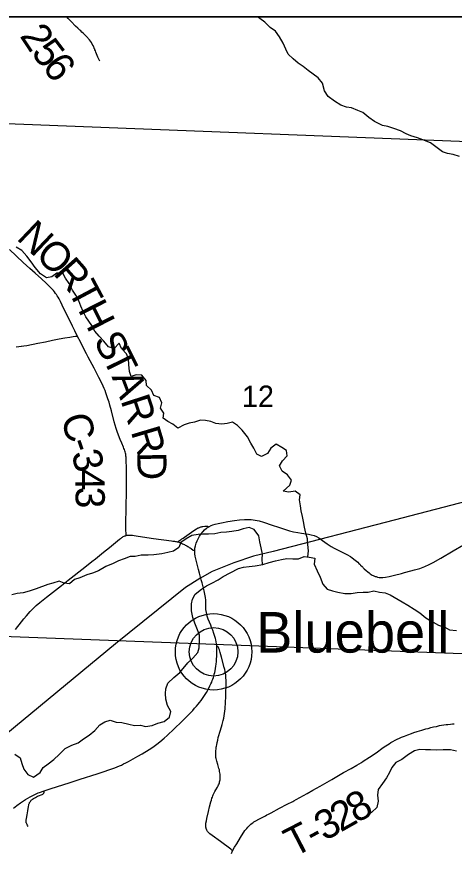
# Model space of a CAD drawing. Extents: x 0 to 34, y 0 to 22.
# Drawn here: x 4.44 to 5.291, y 19.271 to 20.9 of the extents above; entities that cross this region are included whole.
import ezdxf

# ---------------------------------------------------------------- set-up
doc = ezdxf.new("R2010")
doc.units = 0
for name, color, linetype in [('GM_X_Corporation', 7, 'Continuous'), ('GM_X_County_Road', 7, 'Continuous'), ('GM_X_County_Road_Text', 7, 'Continuous'), ('GM_X_Minor_River', 7, 'Continuous'), ('GM_X_Rail_Line', 7, 'Continuous'), ('GM_X_Section_Text', 7, 'Continuous'), ('GM_X_State_Route', 7, 'Continuous'), ('GM_X_Township_Road', 7, 'Continuous'), ('GM_X_Township_Road_Text', 7, 'Continuous'), ('GM_X_Unincorporated', 7, 'Continuous'), ('GM_X_Unincorporated_Location', 7, 'Continuous'), ('GM_X_Unincorporated_Text', 7, 'Continuous'), ('SH_Data', 7, 'Continuous')]:
    doc.layers.add(name, color=color, linetype=linetype)

msp = doc.modelspace()

# ---------------------------------------------------------------- linework, layer by layer
at = {"layer": 'GM_X_Corporation'}
for points in [[(8.9, 20.9), (2.1, 20.9), (2.1, 15.6606)], [(8.9, 20.9), (3.3886, 20.9), (3.3869, 20.7918), (3.3724, 19.7263), (3.3691, 19.5041), (3.3642, 18.7005)]]:
    msp.add_lwpolyline(points, dxfattribs=at)
for points in [[(5.4364, 20.9), (4.4076, 20.9), (4.4032, 20.6929), (5.4344, 20.6525)], [(5.4344, 20.6525), (5.4328, 20.6183), (5.4095, 19.6556), (4.3939, 19.6935), (4.4032, 20.6929)]]:
    msp.add_lwpolyline(points, close=True, dxfattribs=at)
at = {"layer": 'GM_X_County_Road'}
for points in [[(4.5583, 20.2776), (4.553, 20.2883), (4.5487, 20.2972), (4.5286, 20.3386), (4.5249, 20.3457), (4.5222, 20.3507), (4.5204, 20.3537), (4.5187, 20.3566), (4.5172, 20.359), (4.5155, 20.3613), (4.5135, 20.364), (4.5112, 20.3666), (4.5084, 20.3698), (4.5053, 20.3731), (4.4974, 20.3811), (4.4883, 20.3896), (4.4756, 20.4007), (4.4653, 20.4095), (4.4522, 20.4211), (4.4256, 20.4464)], [(4.5583, 20.2776), (4.5541, 20.277), (4.55, 20.2765), (4.5433, 20.2755), (4.5334, 20.2739), (4.5224, 20.2718), (4.5097, 20.2692), (4.4958, 20.2664), (4.4812, 20.2634), (4.4599, 20.2592), (4.4538, 20.2583), (4.4495, 20.2577), (4.4483, 20.2576), (4.444, 20.257), (4.4387, 20.2566)], [(4.6531, 19.8898), (4.6528, 19.8926), (4.6526, 19.8954), (4.6524, 19.898), (4.6522, 19.9016), (4.6521, 19.9071), (4.6521, 19.9114), (4.6521, 19.9195), (4.6527, 19.9362), (4.6531, 19.9467), (4.6535, 19.9743), (4.6536, 19.9923), (4.6537, 20.0096), (4.6536, 20.019), (4.6534, 20.0258), (4.6531, 20.0314), (4.6528, 20.037), (4.6526, 20.0424), (4.6524, 20.0443), (4.6522, 20.0462), (4.6519, 20.0481), (4.6515, 20.05), (4.6508, 20.0525), (4.6501, 20.0549), (4.6493, 20.057), (4.6484, 20.0594), (4.6475, 20.0619), (4.6444, 20.0693), (4.6412, 20.0768), (4.6361, 20.0901), (4.6333, 20.0983), (4.6295, 20.1114), (4.6242, 20.1325), (4.6213, 20.1433), (4.6195, 20.1494), (4.6174, 20.1558), (4.6154, 20.1617), (4.6134, 20.1676), (4.6117, 20.172), (4.61, 20.1763), (4.6059, 20.1854), (4.5999, 20.1977), (4.5903, 20.2159), (4.5789, 20.2372), (4.5755, 20.2438), (4.5682, 20.2582), (4.5637, 20.2669), (4.5583, 20.2776)], [(4.7534, 19.8773), (4.7549, 19.8786), (4.7567, 19.88), (4.7585, 19.8814), (4.7597, 19.8822), (4.7609, 19.8831), (4.7635, 19.8847), (4.7661, 19.8864), (4.7709, 19.8897), (4.7757, 19.8933), (4.7843, 19.8993), (4.7895, 19.9026), (4.7917, 19.9038), (4.7929, 19.9044), (4.794, 19.905), (4.7953, 19.9056), (4.7966, 19.906), (4.7979, 19.9065), (4.7992, 19.9069), (4.8006, 19.9072), (4.802, 19.9075), (4.8057, 19.908), (4.8087, 19.9081), (4.8099, 19.908), (4.8111, 19.9078), (4.8126, 19.9073), (4.8138, 19.9069)], [(4.4377, 19.7069), (4.4493, 19.7218), (4.4539, 19.7277), (4.4587, 19.7334), (4.466, 19.7417), (4.4721, 19.7479), (4.4748, 19.7505), (4.478, 19.7534), (4.4846, 19.759), (4.4977, 19.7695), (4.527, 19.7925), (4.5402, 19.8028), (4.5725, 19.828), (4.5861, 19.8388), (4.5929, 19.8442), (4.6089, 19.8571), (4.6204, 19.8666), (4.6281, 19.8729), (4.6401, 19.8827), (4.6415, 19.8838), (4.6429, 19.8848), (4.6443, 19.8858), (4.6458, 19.8868), (4.6472, 19.8875), (4.6488, 19.8883), (4.6501, 19.8889), (4.6514, 19.8894), (4.6531, 19.8898)], [(4.6531, 19.8898), (4.6546, 19.8902), (4.6562, 19.8905), (4.6575, 19.8906), (4.659, 19.8907), (4.6605, 19.8907), (4.6621, 19.8906), (4.6636, 19.8905), (4.665, 19.8903), (4.6683, 19.8898), (4.6763, 19.8886), (4.7057, 19.884), (4.7411, 19.8792), (4.7439, 19.8788), (4.7468, 19.8784), (4.7485, 19.8782), (4.7501, 19.878), (4.7518, 19.8777), (4.7534, 19.8773)], [(4.7534, 19.8773), (4.7552, 19.8767), (4.757, 19.876), (4.7589, 19.8753), (4.7607, 19.8745), (4.7625, 19.8737), (4.7644, 19.8728), (4.766, 19.8721), (4.7677, 19.8712), (4.7694, 19.8703), (4.771, 19.8694), (4.7725, 19.8686), (4.7741, 19.8676), (4.7757, 19.8667), (4.7775, 19.8655), (4.779, 19.8645), (4.7834, 19.8615), (4.7864, 19.8596)]]:
    msp.add_lwpolyline(points, dxfattribs=at)
at = {"layer": 'GM_X_Minor_River'}
for points in [[(5.0071, 20.7954), (4.9972, 20.8029), (4.9877, 20.8096), (4.9774, 20.8178), (4.9679, 20.8268), (4.9636, 20.8366), (4.9583, 20.8487), (4.9513, 20.8611), (4.9433, 20.8717), (4.933, 20.8791), (4.9227, 20.8896), (4.9128, 20.8963), (4.9084, 20.9)], [(5.3011, 20.628), (5.289, 20.6317), (5.278, 20.6334), (5.2682, 20.6371), (5.2446, 20.6543), (5.2302, 20.6602), (5.2196, 20.6643), (5.2067, 20.6679), (5.1972, 20.672), (5.1862, 20.6776), (5.1737, 20.6824), (5.1619, 20.686), (5.1517, 20.6882), (5.1357, 20.696), (5.1247, 20.7038), (5.1129, 20.7132), (5.1034, 20.7172), (5.0909, 20.7228), (5.0811, 20.7242), (5.0701, 20.7279), (5.0579, 20.7353), (5.0457, 20.7447), (5.0384, 20.756), (5.0345, 20.7703), (5.0261, 20.7812), (5.0071, 20.7954)], [(5.0062, 19.8481), (5.0077, 19.8599), (5.0065, 19.872), (5.0053, 19.883), (5.0025, 19.894), (4.9994, 19.9057), (4.9978, 19.917), (4.9958, 19.9269), (4.9934, 19.9378), (4.9918, 19.9477), (4.9898, 19.959), (4.9916, 19.9689), (4.9814, 19.976), (4.9693, 19.9739), (4.9579, 19.9761), (4.9711, 19.988), (4.9744, 19.9975), (4.9667, 20.008), (4.9561, 20.0151), (4.9511, 20.0257), (4.9571, 20.0352), (4.966, 20.0451), (4.9648, 20.055), (4.9553, 20.0609), (4.9443, 20.0673), (4.9345, 20.0596), (4.9278, 20.0497), (4.9161, 20.0439), (4.9067, 20.0483), (4.9013, 20.0596), (4.8951, 20.0694), (4.889, 20.0822), (4.8787, 20.0946), (4.8691, 20.104), (4.8596, 20.1103), (4.8494, 20.1079), (4.8389, 20.1063), (4.8275, 20.1077), (4.8177, 20.1118), (4.807, 20.1139), (4.7972, 20.1142), (4.7855, 20.1103), (4.7757, 20.1083), (4.7655, 20.1055), (4.7535, 20.0986), (4.7436, 20.1068), (4.7341, 20.112), (4.7246, 20.118), (4.7264, 20.1279), (4.7199, 20.1377), (4.7221, 20.1483), (4.7178, 20.1588), (4.7068, 20.1625), (4.7022, 20.1727), (4.6927, 20.1817), (4.6918, 20.1919), (4.683, 20.2021), (4.6721, 20.2027), (4.6623, 20.1992), (4.6592, 20.2094), (4.6583, 20.223), (4.6571, 20.234), (4.6532, 20.2438), (4.644, 20.2539), (4.639, 20.2641), (4.6293, 20.2541), (4.6187, 20.2574), (4.6091, 20.2683), (4.6, 20.2781), (4.592, 20.2879), (4.5858, 20.2984), (4.5743, 20.3157), (4.5689, 20.3259), (4.5647, 20.3361), (4.5608, 20.3466), (4.5551, 20.3579), (4.5482, 20.3677), (4.542, 20.3802), (4.5347, 20.3907), (4.529, 20.4016), (4.518, 20.4007), (4.5082, 20.3938), (4.4981, 20.3914), (4.4859, 20.3996), (4.4756, 20.4117), (4.4683, 20.423), (4.4599, 20.4339), (4.45, 20.4447), (4.4386, 20.4511)], [(4.918, 19.8332), (4.9171, 19.8434), (4.9182, 19.8533), (4.9154, 19.8658), (4.9127, 19.8771), (4.9111, 19.8892), (4.9019, 19.9013), (4.892, 19.9053), (4.8807, 19.9029), (4.8709, 19.8998), (4.8581, 19.8978), (4.8483, 19.8965), (4.8369, 19.8953), (4.8252, 19.8932), (4.8128, 19.8924), (4.8029, 19.8923), (4.7931, 19.8914), (4.7803, 19.8897), (4.7694, 19.8832), (4.7592, 19.8763), (4.7555, 19.8664), (4.745, 19.8591), (4.7341, 19.8567), (4.7224, 19.8543), (4.7065, 19.8518), (4.6959, 19.8514), (4.6819, 19.8512), (4.6706, 19.8488), (4.6604, 19.8491), (4.6487, 19.8444), (4.6378, 19.8401), (4.6273, 19.8351), (4.6133, 19.8293), (4.5987, 19.8212), (4.5874, 19.8165), (4.5761, 19.813), (4.5629, 19.8075), (4.5523, 19.804), (4.5426, 19.7959), (4.532, 19.7966), (4.5225, 19.8007), (4.5104, 19.7971), (4.5002, 19.794), (4.4776, 19.7862), (4.4644, 19.7815), (4.4524, 19.7783), (4.441, 19.7767), (4.4305, 19.7743)], [(4.4729, 19.419), (4.4853, 19.4282), (4.4912, 19.4378), (4.501, 19.4454), (4.5119, 19.4535), (4.5224, 19.4631), (4.5344, 19.475), (4.5472, 19.4815), (4.5592, 19.4862), (4.5698, 19.4935), (4.5807, 19.5012), (4.5919, 19.51), (4.6017, 19.5208), (4.6114, 19.5269), (4.6216, 19.5304), (4.6334, 19.5264), (4.6447, 19.5254), (4.6583, 19.5225), (4.6693, 19.5199), (4.6807, 19.5204), (4.6905, 19.5179), (4.7037, 19.5195), (4.7147, 19.5242), (4.7267, 19.5274), (4.7369, 19.5358), (4.7398, 19.5468), (4.7333, 19.5585), (4.7297, 19.5713), (4.7293, 19.5819), (4.7303, 19.5914), (4.734, 19.6021), (4.7456, 19.6132), (4.7569, 19.6228), (4.7726, 19.6419), (4.7824, 19.6511), (4.7925, 19.6618), (4.7947, 19.6713), (4.7953, 19.6838), (4.7956, 19.6955), (4.7917, 19.7061), (4.7863, 19.7193), (4.7824, 19.7303), (4.78, 19.7431), (4.7799, 19.7564), (4.7821, 19.7659), (4.7869, 19.7758), (4.7993, 19.785), (4.8091, 19.7919), (4.8193, 19.797), (4.8321, 19.8035), (4.8418, 19.8101), (4.855, 19.817), (4.8712, 19.8252), (4.881, 19.8279), (4.8923, 19.8295), (4.904, 19.8304), (4.9184, 19.8332), (4.9312, 19.8372), (4.9433, 19.8403), (4.9549, 19.8431), (4.9655, 19.8447), (4.9769, 19.8445), (4.9882, 19.8446), (4.9991, 19.8489), (5.009, 19.8478), (5.0196, 19.8453), (5.0182, 19.8339), (5.0243, 19.8207), (5.0305, 19.8086), (5.0355, 19.7951), (5.0439, 19.7853), (5.0541, 19.782), (5.0647, 19.7795), (5.0784, 19.7769), (5.0905, 19.7771), (5.1022, 19.7787), (5.1139, 19.7792), (5.1237, 19.7797), (5.1347, 19.7817), (5.1456, 19.7795), (5.1566, 19.7781), (5.1661, 19.7741), (5.1897, 19.7607), (5.2007, 19.7544), (5.2132, 19.7462), (5.2242, 19.7391), (5.236, 19.7294), (5.2497, 19.7208), (5.2604, 19.7152), (5.2725, 19.7112), (5.282, 19.7063), (5.2952, 19.7046)], [(5.2954, 19.4697), (5.2836, 19.4726), (5.2697, 19.4725), (5.2564, 19.4716), (5.2451, 19.4726), (5.2349, 19.4721), (5.2239, 19.4731), (5.2134, 19.4703), (5.2021, 19.4634), (5.1893, 19.4538), (5.1773, 19.4476), (5.1698, 19.4381), (5.165, 19.4285), (5.159, 19.4179), (5.1512, 19.4068), (5.1433, 19.3954), (5.1419, 19.384), (5.1428, 19.3722), (5.1406, 19.3601), (5.1305, 19.3509), (5.1207, 19.344), (5.1222, 19.3428)], [(4.4362, 19.4641), (4.4465, 19.457), (4.45, 19.446), (4.4538, 19.4347), (4.4615, 19.4242), (4.4729, 19.419)]]:
    msp.add_lwpolyline(points, dxfattribs=at)
at = {"layer": 'GM_X_Rail_Line'}
msp.add_lwpolyline([(7.1041, 20.4576), (6.548, 20.2811), (6.4552, 20.2522), (5.6204, 20.0355), (5.1742, 19.9198), (4.9387, 19.8589), (4.9007, 19.8493), (4.8622, 19.8368), (4.8204, 19.8197), (4.7961, 19.8057), (4.7682, 19.7883), (4.6322, 19.6788), (3.9277, 19.0962), (3.874, 19.0476), (3.8339, 19.0097), (3.7908, 18.9611), (3.75, 18.9158), (3.7169, 18.8748), (3.6829, 18.8279), (3.1625, 18.0833)], dxfattribs=at)
at = {"layer": 'GM_X_State_Route'}
msp.add_lwpolyline([(4.4337, 19.359), (4.4402, 19.3639), (4.4475, 19.369), (4.4573, 19.3754), (4.4664, 19.3807), (4.4703, 19.383), (4.4739, 19.3849), (4.4763, 19.3861), (4.4788, 19.3872), (4.4815, 19.3884), (4.4843, 19.3894), (4.4935, 19.3927), (4.5047, 19.3962), (4.5439, 19.4088), (4.5635, 19.4151), (4.5966, 19.4259), (4.6099, 19.4303), (4.6193, 19.4335), (4.6248, 19.4354), (4.6307, 19.4376), (4.6355, 19.4394), (4.6399, 19.4412), (4.6435, 19.4428), (4.6478, 19.4448), (4.6525, 19.4471), (4.6576, 19.4498), (4.6618, 19.452), (4.6663, 19.4546), (4.6754, 19.4598), (4.6838, 19.4647), (4.6973, 19.4731), (4.7026, 19.4765), (4.7072, 19.4796), (4.7123, 19.4833), (4.7182, 19.4878), (4.7268, 19.495), (4.7324, 19.5), (4.7464, 19.5132), (4.761, 19.5275), (4.7758, 19.5426), (4.7823, 19.5492), (4.786, 19.5532), (4.7898, 19.5575), (4.7928, 19.5611), (4.7957, 19.5647), (4.7985, 19.5683), (4.8013, 19.5723), (4.8038, 19.5759), (4.8064, 19.58), (4.8088, 19.584), (4.8115, 19.5886), (4.8136, 19.5926), (4.8158, 19.5969), (4.8175, 19.6006), (4.8192, 19.6043), (4.8204, 19.6073), (4.8214, 19.6101), (4.8224, 19.6133), (4.8233, 19.6161), (4.8242, 19.6194), (4.825, 19.6227), (4.8258, 19.6264), (4.8266, 19.6307), (4.8272, 19.6352), (4.8278, 19.6393), (4.8283, 19.6444), (4.8287, 19.6493), (4.829, 19.6542), (4.8292, 19.6593), (4.8293, 19.6636), (4.8292, 19.668), (4.8289, 19.6746), (4.8287, 19.6791), (4.8281, 19.6829), (4.8272, 19.6865), (4.8265, 19.6894), (4.8249, 19.6947), (4.8235, 19.6988), (4.8212, 19.7052), (4.8189, 19.7109), (4.8173, 19.7149), (4.8125, 19.727), (4.8105, 19.7329), (4.809, 19.7396), (4.8081, 19.7458), (4.8078, 19.7533), (4.8076, 19.7637), (4.8071, 19.7692), (4.8061, 19.7753), (4.8047, 19.7819), (4.802, 19.7927), (4.8007, 19.7974), (4.8, 19.7998), (4.799, 19.8034), (4.7976, 19.8088), (4.7955, 19.8166), (4.7935, 19.8238), (4.7908, 19.834), (4.7882, 19.8443), (4.7872, 19.8498), (4.7866, 19.8542), (4.7864, 19.8596), (4.7867, 19.8649), (4.7876, 19.8699), (4.7889, 19.8748), (4.7907, 19.8795), (4.7926, 19.8835), (4.7954, 19.8884), (4.7987, 19.893), (4.8023, 19.8974), (4.8055, 19.9005), (4.8093, 19.9038), (4.8138, 19.9069), (4.818, 19.9091), (4.8215, 19.9105), (4.8257, 19.9119), (4.8318, 19.9133), (4.8385, 19.9145), (4.8508, 19.9167), (4.8637, 19.9188), (4.8736, 19.92), (4.8829, 19.9208), (4.8892, 19.9209), (4.8961, 19.9208), (4.9036, 19.9198), (4.9115, 19.918), (4.9199, 19.9156), (4.9371, 19.91), (4.9494, 19.9058), (4.9606, 19.9021), (4.9707, 19.899), (4.9784, 19.897), (4.9869, 19.8954), (4.9937, 19.8943), (5.0072, 19.8921), (5.0127, 19.8911), (5.0182, 19.8897), (5.0229, 19.8878), (5.0273, 19.8853), (5.0345, 19.8803), (5.0441, 19.8734), (5.0513, 19.8686), (5.0577, 19.8649), (5.0637, 19.8618), (5.0704, 19.8586), (5.0743, 19.8567), (5.0766, 19.8556), (5.0821, 19.8527), (5.0891, 19.8486), (5.0927, 19.8461), (5.0982, 19.8419), (5.1034, 19.8375), (5.1056, 19.8354), (5.1073, 19.8337), (5.1079, 19.833), (5.1088, 19.832), (5.1117, 19.8291), (5.113, 19.8279), (5.1138, 19.8271), (5.1159, 19.825), (5.1194, 19.8219), (5.1203, 19.8211), (5.1221, 19.8195), (5.123, 19.8187), (5.1253, 19.8169), (5.1272, 19.8154), (5.1296, 19.8137), (5.1312, 19.8128), (5.1332, 19.8118), (5.1371, 19.8102), (5.1388, 19.8097), (5.1416, 19.8088), (5.1451, 19.8082), (5.1487, 19.808), (5.1523, 19.8081), (5.1571, 19.8087), (5.1644, 19.8102), (5.1747, 19.8126), (5.1885, 19.816), (5.1945, 19.8175), (5.1969, 19.8182), (5.2137, 19.8227), (5.2238, 19.8258), (5.2336, 19.8294), (5.2421, 19.8331), (5.2503, 19.8374), (5.2649, 19.8457), (5.2889, 19.8599), (5.3087, 19.8717)], dxfattribs=at)
at = {"layer": 'GM_X_Township_Road'}
msp.add_line((4.8576, 19.2704), (4.8599, 19.2758), dxfattribs=at)
for points in [[(4.6017, 20.8135), (4.598, 20.8214), (4.5953, 20.8277), (4.5939, 20.8311), (4.593, 20.8333), (4.5921, 20.8355), (4.5916, 20.8366), (4.5909, 20.8383), (4.5904, 20.8394), (4.59, 20.8405), (4.5885, 20.8438), (4.587, 20.8468), (4.5851, 20.8497), (4.5834, 20.8523), (4.5813, 20.8553), (4.5792, 20.8576), (4.5781, 20.859), (4.5764, 20.8609), (4.5739, 20.8635), (4.5716, 20.8656), (4.5694, 20.8678), (4.5667, 20.8702), (4.5645, 20.8724), (4.5627, 20.8741), (4.5591, 20.8775), (4.5546, 20.8818), (4.5458, 20.8905), (4.5403, 20.8965), (4.5376, 20.8999), (4.5376, 20.9)], [(4.8599, 19.2758), (4.8561, 19.2789), (4.8364, 19.2939), (4.82, 19.3057), (4.8156, 19.3088), (4.8145, 19.3098), (4.8134, 19.3109), (4.8123, 19.3121), (4.8113, 19.3134), (4.8104, 19.3147), (4.8097, 19.3161), (4.809, 19.3176), (4.8085, 19.3188), (4.8082, 19.3201), (4.8078, 19.3217), (4.8077, 19.3233), (4.8076, 19.3246), (4.8077, 19.3259), (4.8078, 19.3277), (4.8081, 19.3297), (4.809, 19.3342), (4.81, 19.3389), (4.8131, 19.3522), (4.815, 19.3613), (4.8174, 19.371), (4.8185, 19.3746), (4.8196, 19.3782), (4.8205, 19.3805), (4.8212, 19.3826), (4.822, 19.3844), (4.8227, 19.3859), (4.8233, 19.3872), (4.8241, 19.3885), (4.8256, 19.3914), (4.8275, 19.3945), (4.8306, 19.3998), (4.8318, 19.4021), (4.8327, 19.4042), (4.8335, 19.4061), (4.8342, 19.4082), (4.8346, 19.4098), (4.835, 19.4117), (4.8354, 19.4139), (4.8356, 19.4159), (4.8358, 19.418), (4.8358, 19.4201), (4.8357, 19.4226), (4.8355, 19.4249), (4.8352, 19.4276), (4.8347, 19.4303), (4.8341, 19.4332), (4.8333, 19.4362), (4.831, 19.4438), (4.8292, 19.45), (4.828, 19.4552), (4.8275, 19.4577), (4.8272, 19.4601), (4.8271, 19.4627), (4.8271, 19.4651), (4.8271, 19.4678), (4.8273, 19.4707), (4.8276, 19.4741), (4.8281, 19.4775), (4.8285, 19.4798), (4.8289, 19.4823), (4.8298, 19.4866), (4.8309, 19.4914), (4.8321, 19.4962), (4.8362, 19.5104), (4.8396, 19.5215), (4.8416, 19.5292), (4.8426, 19.534), (4.8435, 19.5388), (4.8442, 19.5432), (4.8449, 19.5479), (4.8454, 19.5521), (4.8457, 19.5564), (4.846, 19.5616), (4.8462, 19.5668), (4.8464, 19.5744), (4.8466, 19.5821), (4.8472, 19.5987), (4.8473, 19.602), (4.8473, 19.6053), (4.8472, 19.6085), (4.847, 19.6121), (4.8468, 19.6153), (4.8465, 19.6182), (4.846, 19.6216), (4.8454, 19.625), (4.8446, 19.6288), (4.8436, 19.6325), (4.838, 19.6526), (4.8359, 19.6616), (4.8351, 19.6644), (4.8344, 19.667), (4.8334, 19.67), (4.8326, 19.6718), (4.8319, 19.6728), (4.8305, 19.6739), (4.8289, 19.6746)], [(4.8599, 19.2758), (4.8637, 19.2825), (4.8678, 19.2896), (4.8752, 19.3018), (4.8801, 19.3098), (4.8814, 19.3118), (4.8839, 19.3151), (4.8853, 19.3169), (4.8874, 19.3194), (4.8893, 19.3216), (4.8932, 19.3255), (4.8956, 19.3277), (4.8978, 19.3294), (4.8998, 19.3309), (4.9013, 19.332), (4.9048, 19.3342), (4.9108, 19.3374), (4.9239, 19.3441), (4.9267, 19.3456), (4.9299, 19.3472), (4.9347, 19.3497), (4.951, 19.3585), (4.9658, 19.3663), (4.9768, 19.372), (4.979, 19.3731), (4.9834, 19.3754), (5.0051, 19.3874), (5.0159, 19.3935), (5.0304, 19.4017), (5.0438, 19.4095), (5.053, 19.4148), (5.0757, 19.428), (5.0902, 19.4361), (5.1014, 19.4425), (5.1104, 19.4479), (5.1141, 19.4502), (5.1261, 19.458), (5.1388, 19.4668), (5.153, 19.4768), (5.1582, 19.4804), (5.1644, 19.4843), (5.1678, 19.4864), (5.1718, 19.4887), (5.1762, 19.491), (5.18, 19.493), (5.1847, 19.4952), (5.1884, 19.4968), (5.194, 19.4992), (5.2005, 19.5018), (5.2078, 19.5044), (5.2127, 19.5061), (5.219, 19.5081), (5.2234, 19.5094), (5.2278, 19.5108), (5.2317, 19.5119), (5.236, 19.5131), (5.24, 19.5142), (5.2454, 19.5156), (5.2508, 19.517), (5.2562, 19.5181), (5.2586, 19.5187), (5.2622, 19.5195), (5.2659, 19.5202), (5.2708, 19.521), (5.2752, 19.5216), (5.2787, 19.522), (5.2834, 19.5226), (5.2879, 19.5229), (5.291, 19.5232)], [(4.462, 19.3233), (4.4611, 19.3248), (4.4601, 19.3267), (4.4594, 19.3282), (4.4589, 19.3293), (4.4586, 19.3305), (4.4584, 19.332), (4.4584, 19.3335), (4.4586, 19.3355), (4.4589, 19.3388), (4.46, 19.3458), (4.4613, 19.3536), (4.4627, 19.3622), (4.4633, 19.3647), (4.4638, 19.3665), (4.4641, 19.3677), (4.4646, 19.3687), (4.4651, 19.3698), (4.4658, 19.371), (4.4665, 19.372), (4.4674, 19.373), (4.4683, 19.3741), (4.4695, 19.3752), (4.4708, 19.3763), (4.4725, 19.3774), (4.4742, 19.3785), (4.4762, 19.3797), (4.4782, 19.3808), (4.4806, 19.3819), (4.4842, 19.3834), (4.4875, 19.3848), (4.4897, 19.3856), (4.4908, 19.3862), (4.4915, 19.3867), (4.4922, 19.3873), (4.4926, 19.3879), (4.493, 19.3885), (4.4933, 19.3892), (4.4935, 19.3899), (4.4936, 19.3906), (4.4936, 19.3914), (4.4935, 19.3927)]]:
    msp.add_lwpolyline(points, dxfattribs=at)
at = {"layer": 'GM_X_Unincorporated'}
for radius in [0.0744, 0.0472]:
    msp.add_circle((4.8229, 19.6632), radius, dxfattribs=at)
at = {"layer": 'GM_X_Unincorporated_Location'}
msp.add_line((4.8229, 19.6632), (4.8229, 19.6632), dxfattribs=at)
at = {"layer": 'SH_Data'}
msp.add_line((2.1, 20.9), (8.9, 20.9), dxfattribs=at)

# ---------------------------------------------------------------- texts
at = {"layer": 'GM_X_County_Road_Text'}
for s, rotation, p in [('N', 316.4633, (4.4378, 20.4675)), ('O', 316.4026, (4.474, 20.433)), ('R', 311.6089, (4.5093, 20.3995)), ('T', 298.0218, (4.5383, 20.3675)), ('H', 296.8379, (4.5581, 20.3302)), ('S', 296.8062, (4.5886, 20.27)), ('T', 296.3025, (4.6058, 20.2359)), ('A', 290.8767, (4.6241, 20.1991)), ('R', 288.0888, (4.6417, 20.1531)), ('C', 285.3943, (4.5256, 20.1197)), ('R', 286.6981, (4.6615, 20.0925)), ('-', 288.9757, (4.5391, 20.071)), ('3', 283.2903, (4.5463, 20.0504)), ('D', 271.2131, (4.6742, 20.0518)), ('4', 270.6297, (4.5539, 20.0196)), ('3', 270.4944, (4.5543, 19.9846))]:
    msp.add_text(s, height=0.0568, rotation=rotation, dxfattribs=at).set_placement(p)
at = {"layer": 'GM_X_Section_Text'}
msp.add_text('12', height=0.04186, rotation=0, dxfattribs=at).set_placement((4.878, 20.1398))
at = {"layer": 'GM_X_Township_Road_Text'}
for s, rotation, p in [('2', 303.3064, (4.4448, 20.8627)), ('5', 307.4465, (4.4666, 20.8298)), ('6', 307.4179, (4.4879, 20.802)), ('8', 29.6297, (5.1006, 19.3285)), ('2', 29.5085, (5.07, 19.3112)), ('3', 29.053, (5.039, 19.2939)), ('T', 27.2896, (4.979, 19.2624)), ('-', 28.5689, (5.018, 19.2825))]:
    msp.add_text(s, height=0.0568, rotation=rotation, dxfattribs=at).set_placement(p)
at = {"layer": 'GM_X_Unincorporated_Text'}
msp.add_text('Bluebell', height=0.07898, rotation=0, dxfattribs=at).set_placement((4.9057, 19.6617))

doc.saveas('drawing.dxf')
